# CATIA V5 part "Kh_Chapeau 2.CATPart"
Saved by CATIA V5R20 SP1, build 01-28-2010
Part number: Chapeau 2
Bounding box of the stored display mesh (mm): x -41.992 to 41.992, y -6 to 0, z -41.992 to 41.992
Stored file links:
  G:\Khaled_CFAO_2011\SIL\SIL_GR1\tmerino\Khaled\CAD_Thinkmotion\Kh_Chapeau 2.CATPart
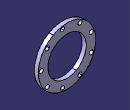
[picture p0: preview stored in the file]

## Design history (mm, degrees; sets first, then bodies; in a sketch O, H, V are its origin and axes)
Body1 (main body)
  Sketch1 on yz-plane, origin (0, 0, 0), H (0, 1, 0), V (0, 0, 1)
    line L1 (-6, -28) -> (0, -28)
    line L2 (0, -28) -> (0, -42)
    line L3 (0, -42) -> (-6, -42)
    line L4 (-6, -42) -> (-6, -28)
    distance H L1 = 28
    distance L4 L2 = 6
    distance L3 H = 42
    distance L2 V = 0
    horizontal: L1 H, L3 H
    vertical: L2 V, L4 V
  Shaft1: profile Sketch1, axis Sketch1.H, angle 360
  Sketch2 on face of Shaft1 from Sketch1.L4, origin (34.7794, -6, 7.6368), H (1, 0, 0), V (0, 0, 1)
    point P1 (3.2206, -7.6368)
    reference intersected line E1 through (0, -7.6368) direction (-1, 0) from xy-plane
    reference intersected line E2 through (-34.7794, 0) direction (0, 1) from yz-plane
    distance E1 P1 = 0
    distance E2 P1 = 38
  Hole1: placed by Sketch2, at (38, -6, 0) direction (0, 1, 0), diameter 6, through (limit type 3)
  CircPattern1: of Hole1, instances 9, angular step 40, axis from face of Shaft1 from Sketch1.L4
